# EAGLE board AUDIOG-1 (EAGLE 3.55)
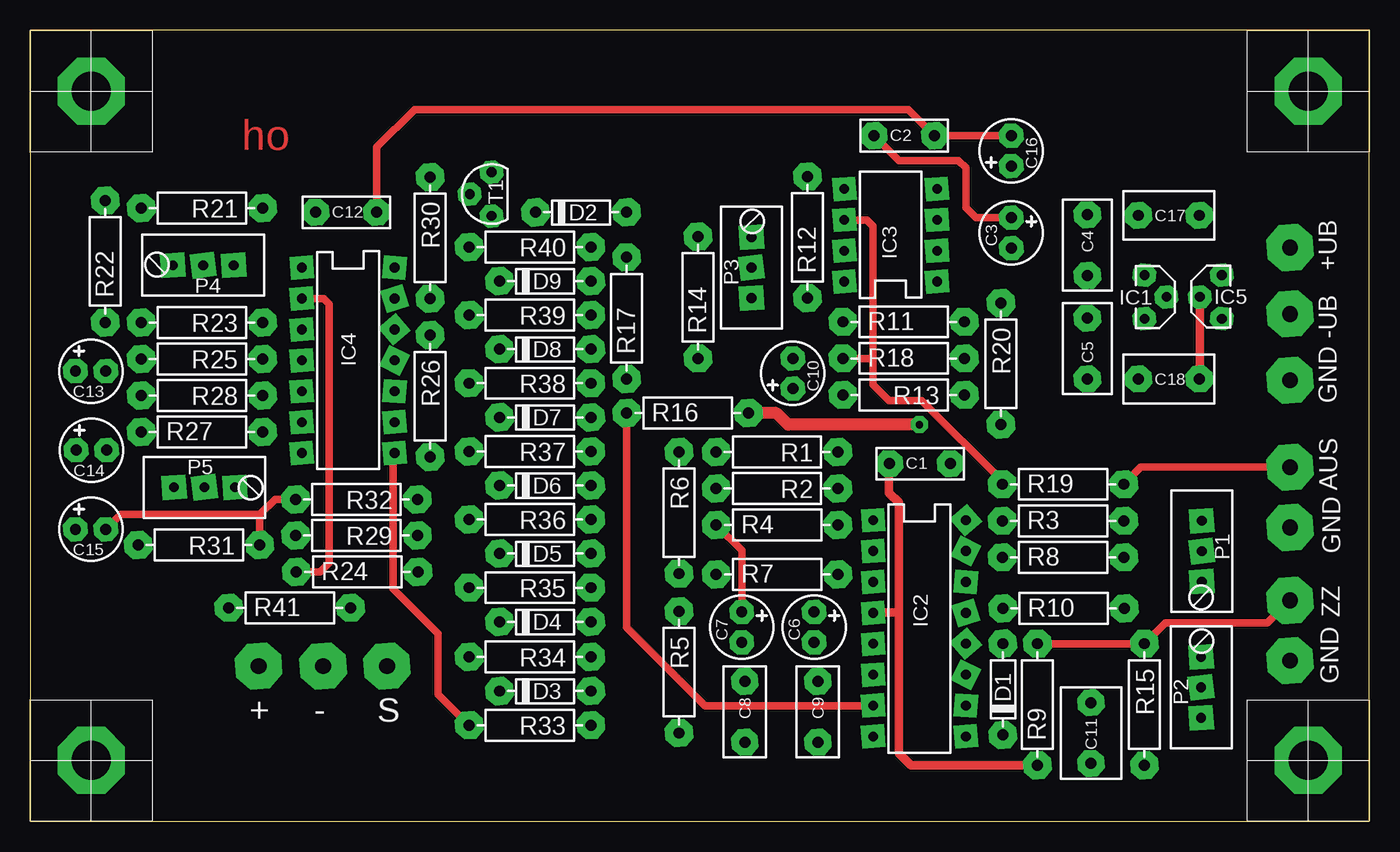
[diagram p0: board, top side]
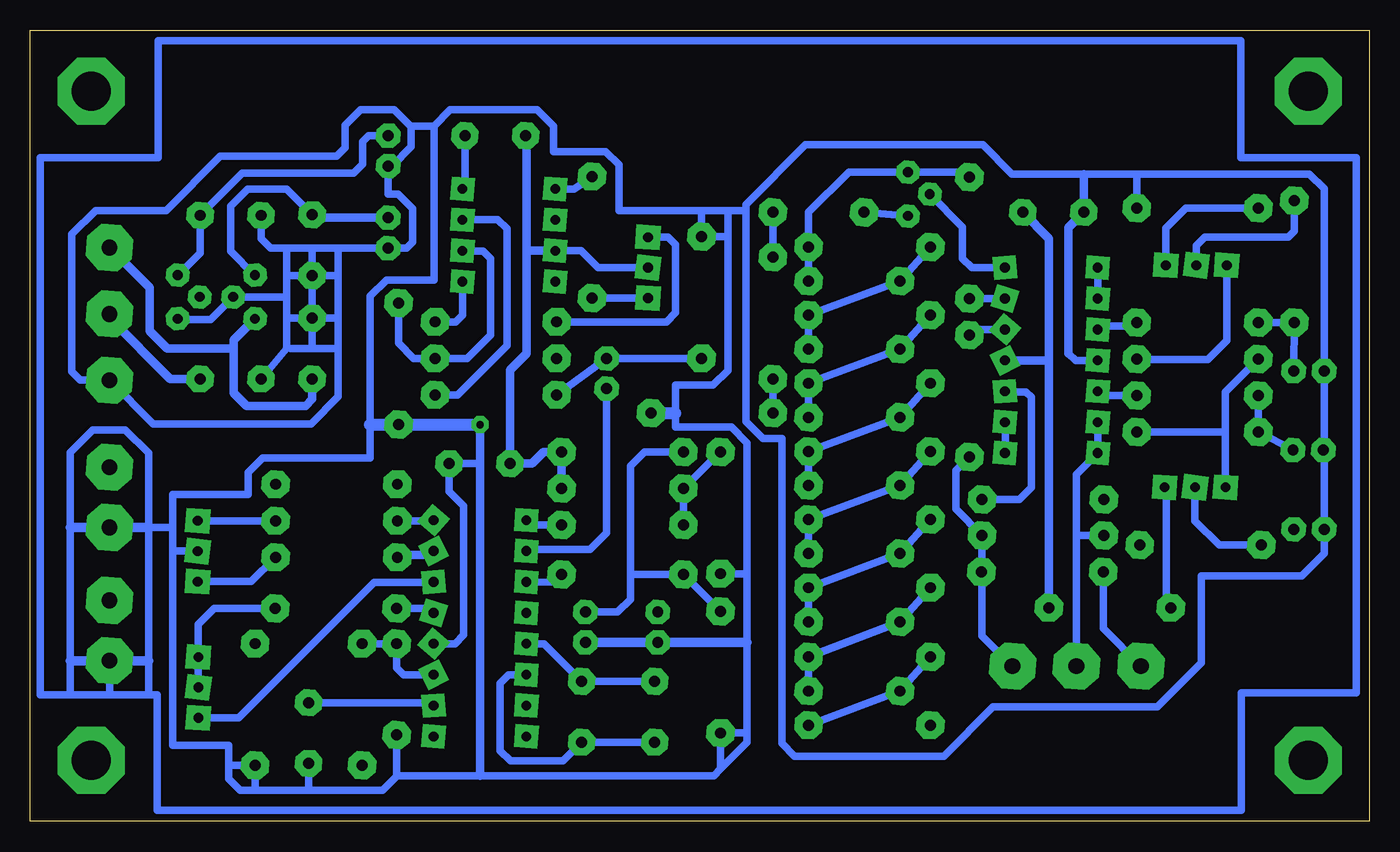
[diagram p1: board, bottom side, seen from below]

Size 110 x 65 mm. Coordinates in mm from the lower left corner, seen from the top.
Outline: 110,0 110,65 0,65 0,0 110,0
Copper layers used: Top, Bottom

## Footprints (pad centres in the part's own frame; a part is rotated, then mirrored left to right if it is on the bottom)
AD-3,8 = drill 1.3 pad 3.8 octagon:  0,0
5-2,8 = drill 0.9 pad 2.2 octagon:  0,0;  5,0
5-R2,5 = drill 0.9 pad 2 octagon:  0,0;  0,2.5
-4,0 = drill 0.9 pad 2.2 octagon:  0,0;  5,0
5-3,5 = drill 0.9 pad 2.2 octagon:  0,0;  5,0
5-5,0 = drill 0.9 pad 2.2 octagon:  0,0;  5,0
7,5 = drill 0.9 pad 2.3 octagon:  0,0;  7.5,0
L00 = drill 0.8 pad 1.9 octagon:  -1.8,1.8;  0,3.6;  0,0
L16 = drill 0.8 pad 1.9 square:  0,0;  2.54,0;  5.08,0;  7.62,0;  10.16,0;  12.7,0;  15.24,0;  17.78,0;  17.78,7.62;  15.24,7.62;  12.7,7.62;  10.16,7.62;  7.62,7.62;  5.08,7.62;  2.54,7.62;  0,7.62
L08 = drill 0.8 pad 1.9 square:  0,0;  2.54,0;  5.08,0;  7.62,0;  7.62,7.62;  5.08,7.62;  2.54,7.62;  0,7.62
L14 = drill 0.8 pad 1.9 square:  0,0;  2.54,0;  5.08,0;  7.62,0;  10.16,0;  12.7,0;  15.24,0;  15.24,7.62;  12.7,7.62;  10.16,7.62;  7.62,7.62;  5.08,7.62;  2.54,7.62;  0,7.62
IMM-S1 = drill 0.8 pad 2 square:  0,0;  2.5,0;  -2.5,0
10 = drill 0.9 pad 2.3 octagon:  0,0;  10,0
-TO92 = drill 0.8 pad 1.9 octagon:  1.8,1.8;  3.6,0;  0,0

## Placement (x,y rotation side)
+  +  [AD-3,8]  18.75,12.75 0 top
+UB  +UB  [AD-3,8]  103.5,47.15 0 top
-  -  [AD-3,8]  24.05,12.75 0 top
-UB  -UB  [AD-3,8]  103.5,41.7 0 top
AUS  Aus  [AD-3,8]  103.5,29.1 0 top
BEF1  [F10]  5,60 0 top
BEF2  [F10]  105,60 0 top
BEF3  [F10]  5,5 0 top
BEF4  [F10]  105,5 0 top
C1  100n  [5-2,8]  70.6,29.4 0 top
C2  100n  [5-2,8]  69.3,56.35 0 top
C3  47u  [5-R2,5]  80.6,47.1 0 top
C4  220n  [-4,0]  86.85,49.85 270 top
C5  330n  [-4,0]  86.85,36.35 90 top
C6  10u  [5-R2,5]  64.4,14.7 0 top
C7  10u  [5-R2,5]  58.45,14.7 0 top
C8  Abgl  [5-3,5]  58.7,11.5 270 top
C9  47n5  [5-3,5]  64.7,11.5 270 top
C10  22u  [5-R2,5]  62.65,38.05 180 top
C11  1u  [5-5,0]  87.15,9.75 270 top
C12  100n  [5-2,8]  23.45,50.05 0 top
C13  22u  [5-R2,5]  6.2,37 90 top
C14  22u  [5-R2,5]  6.25,30.5 90 top
C15  22u  [5-R2,5]  6.2,24 90 top
C16  47u  [5-R2,5]  80.6,56.35 180 top
C17  220n  [-4,0]  91.05,49.8 0 top
C18  330n  [-4,0]  91.05,36.35 0 top
D1  1N4148  [7,5]  79.9,7.1 90 top
D2  1N4148  [7,5]  41.5,50.05 0 top
D3  1N4148  [7,5]  38.55,10.7 0 top
D4  1N4148  [7,5]  38.55,16.4 0 top
D5  1N4148  [7,5]  38.55,22 0 top
D6  1N4148  [7,5]  38.55,27.6 0 top
D7  1N4148  [7,5]  38.55,33.2 0 top
D8  1N4148  [7,5]  38.55,38.8 0 top
D9  1N4148  [7,5]  38.55,44.4 0 top
GND  GND  [AD-3,8]  103.5,36.25 0 top
GND1  [AD-3,8]  103.5,13.2 0 top
GND2  GND  [AD-3,8]  103.5,24.15 0 top
IC1  78L15  [L00]  91.55,44.9 180 top
IC2  XR2206  [L16]  69.25,24.75 270 top
IC3  TL071  [L08]  74.5,44.35 90 top
IC4  TL074  [L14]  22.3,45.5 270 top
IC5  79L15  [L00]  97.9,41.3 0 top
P1  20k  [IMM-S1]  96.25,22.2 270 top
P2  500  [IMM-S1]  96.2,11 90 top
P3  10k  [IMM-S1]  59.25,45.5 90 top
P4  500  [IMM-S1]  14.2,45.7 180 top
P5  200  [IMM-S1]  14.3,27.45 0 top
R1  47k  [10]  66.35,30.35 180 top
R2  82k  [10]  66.35,27.35 180 top
R3  10k  [10]  79.85,24.7 0 top
R4  33k  [10]  56.35,24.35 0 top
R5  47k  [10]  53.3,17.25 270 top
R6  33k  [10]  53.3,30.35 270 top
R7  33k  [10]  56.35,20.3 0 top
R8  10k  [10]  79.85,21.7 0 top
R9  4k7  [10]  82.75,4.6 90 top
R10  120  [10]  79.9,17.5 0 top
R11  4.7k  [10]  66.75,41.05 0 top
R12  4.7k  [10]  63.85,43 90 top
R13  100  [10]  76.75,35.05 180 top
R14  33k  [10]  54.85,38.05 90 top
R15  300  [10]  91.55,14.6 270 top
R16  4M7  [10]  49,33.55 0 top
R17  2k4  [10]  49,36.35 90 top
R18  680  [10]  66.75,38.05 0 top
R19  47  [10]  79.85,27.7 0 top
R20  [10]  79.75,42.6 270 top
R21  3k3  [10]  19.1,50.4 180 top
R22  10k  [10]  6.15,41 90 top
R23  100  [10]  19.1,41 180 top
R24  1M  [10]  21.85,20.5 0 top
R25  2k2  [10]  19.1,38 180 top
R26  100  [10]  32.85,39.95 270 top
R27  10k  [10]  9.1,32 0 top
R28  100  [10]  19.1,35 180 top
R29  1M  [10]  31.8,23.5 180 top
R30  680  [10]  32.85,52.95 270 top
R31  10k  [10]  18.85,22.7 180 top
R32  100  [10]  31.8,26.45 180 top
R33  270  [10]  46.05,7.9 180 top
R34  1k  [10]  46.05,13.5 180 top
R35  2k  [10]  46.05,19.2 180 top
R36  3k9  [10]  46.05,24.8 180 top
R37  8k2  [10]  46.05,30.4 180 top
R38  16k  [10]  46.05,36 180 top
R39  33k  [10]  46.05,41.6 180 top
R40  68k  [10]  46.05,47.2 180 top
R41  1k3  [10]  16.3,17.55 0 top
SCHL  S  [AD-3,8]  29.3,12.75 0 top
T1  BC550C  [-TO92]  37.9,49.75 90 top
Z-OUT  Zum Zhler  [AD-3,8]  103.5,18.15 90 top

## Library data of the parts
+ +UB - -UB AUS GND GND1 GND2 SCHL Z-OUT = PADS
BEF1-BEF4 = MECHANIK
C1-C18 D1-D9 IC2-IC4 R1-R41 T1 = EAGLE
IC1 IC5 = U-STABI
P1-P5 = POTIS

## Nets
+15V: C1. C2. C3. C4. IC1. IC2. IC3. P3. R1. R2. R9.
+UB: +UB. C5. IC1.
-15V: C2. C12. C16. C17. IC3. IC4. IC5. R41.
-UB: -UB. C18. IC5.
AUS: AUS. R19.
GND: C1. C3. C4. C5. C6. C7. C11. C12. C13. C14. C15. C16. C17. C18. D1. GND1. GND2. GND. IC1. IC2. IC4. IC5. P1. R5. R6. R14. R15. R16. R20. R21.
N$1: IC2. R3.
N$2: IC2. R8.
N$3: P1. R3.
N$4: P1. R8.
N$5: IC2. P2.
N$6: IC2. R10.
N$7: P2. R10.
N$8: C6. R1. R5. R7.
N$10: C8. C9. IC2.
N$11: C11. IC2.
N$12: IC2. R4.
N$13: IC2. R7.
N$14: P5. R41.
N$15: C7. R2. R4. R6.
N$16: C10. IC2.
N$17: C10. R13. R14.
N$18: C8. C9. IC2.
N$20: -. IC4. R29.
N$22: IC2. R16. R17.
N$23: +. IC4. R24.
N$24: R24. R26. R29. SCHL.
N$25: P4. R22.
N$26: P5. R31.
N$27: C13. R22. R23.
N$28: IC4. R23.
N$29: P3. R11.
N$30: C15. R31. R32.
N$31: IC4. R32.
N$32: IC4. R26.
N$33: IC4. R33.
N$34: IC4. R28.
N$35: IC3. R13.
N$36: IC3. R18. R20.
N$37: P4. R21.
N$38: P5. R25. R27.
N$39: D9. R30. R40. T1.
N$40: IC4. R30.
N$41: P4. R25.
N$42: P3. R12.
N$43: IC4. T1.
N$44: D3. R33. R34.
N$45: D3. D4. R34. R35.
N$46: D4. D5. R35. R36.
N$47: D5. D6. R36. R37.
N$48: D6. D7. R37. R38.
N$49: D7. D8. R38. R39.
N$50: D8. D9. R39. R40.
N$51: IC3. R18. R19.
N$52: D2. T1.
N$53: D2. R17.
N$56: C14. R27. R28.
N$57: IC3. R12.
N$86: IC3. R11.
TTL-OUT: D1. IC2. R9. R15. Z-OUT.

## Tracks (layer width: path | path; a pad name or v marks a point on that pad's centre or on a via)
+15V
  Top 0.6: C3. 77.7,49.6 76.85,50.45 76.85,53.7 76.25,54.3 71.35,54.3 69.3,56.35
  Top 0.7: 70.6,29.4 70.55,29.4 70.55,27 71.35,26.2 71.35,17.15 | 71.35,17.15 71.35,5.6 72.35,4.6 82.75,4.6 | 69.25,17.13 69.25,17.15 71.35,17.15
  Bottom 0.6: 69.25,56.35 69.3,56.35 | IC1. 91.6,44.9 93.55,46.85 93.55,50.55 92.15,51.95 88.95,51.95 86.85,49.85 | 66.88,46.89 66.85,46.9 64.75,46.9 63.35,45.5 59.25,45.5
  Bottom 0.7: 69.25,46.9 69.25,56.35 | 69.25,46.9 69.25,38.45 70.6,37.1 70.6,29.4 68.8,29.4 67.85,30.35 66.35,30.35 66.35,27.35 | C3. 86.6,49.6 86.85,49.85 | 66.88,46.89 66.9,46.9 69.25,46.9
+UB
  Bottom 0.7: 91.55,41.3 93.3,39.55 93.3,38.85 | 86.85,36.35 86.85,34.7 87.4,34.15 92.25,34.15 93.3,35.2 93.3,38.85 | 93.3,38.85 98.75,38.85 100.2,40.3 100.2,43.85 +UB.
-15V
  Top 0.6: C12. 28.45,55.4 31.55,58.5 72.15,58.5 C2. 80.6,56.35
  Bottom 0.6: 97.9,44.9 97.85,44.9 96.05,46.7 C17. 92.6,53.25 83.45,53.25 82.7,54 82.7,55.85 82.2,56.35 80.6,56.35 | 74.5,51.97 74.3,52.15 C2.
  Bottom 0.7: 29.92,37.88 29.9,37.85 26.3,37.85 | 26.3,37.85 26.3,47.9 C12. | R41. 26.3,37.85
-UB
  Top 0.7: 96.1,43.1 96.1,36.35 C18.
  Bottom 0.7: C18. 98.5,36.35 103.5,41.35 -UB.
AUS
  Top 0.6: R19. 91.25,29.1 AUS.
GND  (via drill 0.6 pad 1.4)
  Top 1: v73.05,32.6 62.25,32.6 61.3,33.55 R16.
  Bottom 0.3: 88.95,41.35 88.95,41.3
  Bottom 0.6: 3.7,30.5 C14. | 3.7,30.5 C13. 3.7,52 4.9,53.2 19.1,53.2 | 3.7,30.5 C15. 3.7,22 5.55,20.15 13.8,20.15 13.8,13 17.4,9.4 30.9,9.4 34.95,5.35 47.2,5.35 48.25,6.4 48.25,31.45 49.8,31.45 51.2,32.85 51.2,50.2 | C1. 75.6,29.35 | C1. 75.6,27.1 74.4,25.9 74.4,15.3 75.1,14.6 76.85,14.6 76.87,14.59 | 73.05,29.4 C1. | C16. 80.6,53.3 | 84.7,47.1 86.85,47.1 | 84.7,47.1 80.6,47.1 79.1,47.1 78.6,47.6 78.6,50.35 79.8,51.55 80.6,51.55 C16. | 84.7,47.1 84.7,44.85 | 84.7,44.85 84.7,41.35 | 86.85,47.1 C4. | C5. 86.85,44.8 | 84.7,44.85 C4. | 88.95,43.1 93.35,43.1 95.2,41.25 97.9,41.25 IC5. | 88.95,44.8 88.95,44.85 C4. | 88.95,44.8 88.95,43.1 | 88.95,43.1 88.95,41.35 C5. | 84.7,41.35 C5. | 84.7,38.85 86.85,38.85 | 86.85,38.85 88.6,38.85 | 84.7,41.35 84.7,38.85 | 84.7,38.85 84.7,34.9 86.95,32.65 99.9,32.65 GND. 105.9,36.25 106.6,36.95 106.6,48.25 104.65,50.2 98.85,50.2 94.4,54.65 84.85,54.65 84.15,55.35 84.15,57.2 82.85,58.5 80.1,58.5 78.75,57.15 | C5. 86.85,38.85 | 88.95,41.3 88.95,38.85 91.05,36.35 | 88.95,47.1 88.95,44.8 | 86.85,47.1 88.95,47.1 | 88.95,47.1 90.25,47.1 91.05,47.9 91.05,49.8 | 22.3,37.88 22.25,37.85 24.1,37.85 24.7,38.45 | 19.1,53.2 19.1,50.4 | 52.7,48.05 52.7,37.05 53.9,35.85 57,35.85 57,33.55 57,32.4 52.4,32.4 51.1,31.1 51.1,20.35 | 52.7,48.05 52.7,50.2 | 52.7,50.2 54.85,50.2 | 54.85,50.2 61.65,50.2 61.65,53.95 62.75,55.05 67,55.05 67,57.15 68.35,58.5 75.5,58.5 76.85,57.15 | 98.3,22.15 98.3,6.25 93.7,6.25 93.7,4.6 | 96.25,22.2 98.3,22.2 98.3,22.15 | 76.85,57.15 76.85,44.5 80.75,44.5 82.1,43.15 82.1,32.6 82.1,29.85 90.9,29.85 92.1,28.65 92.1,26.85 98.3,26.85 98.3,24.15 | C16. 80.3,53.85 78.7,55.45 78.7,57.1 78.75,57.15
  Bottom 0.6: 19.1,53.2 23.45,53.2 29.35,53.2 31.75,55.6 46.3,55.6 51.2,50.7 51.2,50.2 | 51.1,20.35 R6. | 52.7,48.05 R14. 54.85,50.2 | 51.1,7.25 51.1,6.5 53.3,4.3 | 51.1,7.25 51.1,14.7 51.1,20.35 | 53.3,4.3 53.85,3.75 73.05,3.75 79.85,3.75 | 51.1,7.25 R5. 53.3,4.3 | 79.9,7.1 79.9,3.75 79.85,3.75 | 79.85,3.75 81.05,2.55 87.15,2.55 | 91.55,2.55 87.15,2.55 | 91.55,2.55 92.75,2.55 93.7,3.5 93.7,4.6 | 87.15,2.55 C11. | 91.55,2.55 R15. 93.7,4.6 | 98.3,24.15 98.3,22.15 | 106.75,10.4 109.2,10.4 109.2,54.55 99.5,54.55 99.5,64.15 10.55,64.15 10.55,54.55 1.05,54.55 1.05,10.55 10.5,10.55 10.5,0.9 99.6,0.9 99.6,1.7 | 106.75,10.4 103.5,10.4 | 103.5,10.4 100.3,10.4 | 100.3,10.4 99.6,10.4 99.6,1.75 | 100.3,10.4 100.3,13.2 100.3,24.15 | 100.3,24.15 100.3,30.25 102.2,32.15 104.9,32.15 106.75,30.3 106.75,24.15 106.75,13.2 106.75,10.4 | 103.5,10.4 GND1. | 103.45,24.15 GND2. | 100.3,24.15 98.3,24.15 | 52.7,50.2 51.2,50.2 | 76.85,57.15 78.75,57.15
  Bottom 0.7: v73.05,32.6 73.05,29.4 73.05,3.75 | 24.7,38.45 24.7,48.8 23.45,50.05 23.45,53.2
  Bottom 0.8: 64.4,14.7 58.45,14.7 51.1,14.7 | 100.3,13.2 GND1. 106.75,13.2 | 100.3,24.15 103.45,24.15 106.75,24.15
  Bottom 1: 82.1,32.6 R20. v73.05,32.6 | R16. 57,33.55
N$1
  Bottom 0.6: 76.85,24.75 IC2. 77.05,24.7 79.85,24.7
N$2
  Bottom 0.7: 76.87,22.21 77.3,21.9 79.6,21.9 79.85,21.7
N$3
  Bottom 0.6: R3. P1.
N$4
  Bottom 0.6: R8. 91.85,19.7 96.25,19.7
N$5
  Bottom 0.6: 76.87,19.67 76.9,19.65 81.75,19.65 92.9,8.5 P2.
N$6
  Bottom 0.6: 76.87,17.13 77.2,17.5 79.9,17.5
N$7
  Bottom 0.6: 96.2,11 96.2,13.5 96.2,16.2 94.9,17.5 R10.
N$8
  Bottom 0.6: R1. 59.55,30.35 60.7,29.2 60.7,20.3 | 60.7,20.3 60.7,18.25 61.75,17.2 C6. | 60.7,20.3 56.35,20.3 53.3,17.25
N$9  (via drill 3.2 pad 5.5)
  other vias: 5,5
N$10
  Bottom 0.6: 69.25,12.05 70.7,12.05 71.4,11.35 71.4,5.8 70.55,4.95 66.25,4.95 C9. C8.
N$11
  Bottom 0.6: 76.87,9.51 76.9,9.5 77.25,9.75 87.15,9.75
N$12
  Bottom 0.6: 69.25,24.75 69.2,24.75 69.2,24.35 R4.
N$13
  Bottom 0.6: R7. 66.3,20.3 66.95,19.65 69.25,19.67
N$14
  Bottom 0.6: 16.8,27.45 16.65,27.3 16.65,17.9 16.3,17.55
N$15
  Top 0.6: C7. 58.45,22.25 56.35,24.35
  Bottom 0.6: 56.35,24.35 R2. 53.35,30.35 53.3,30.35
N$16
  Bottom 0.6: 69.25,22.2 69.25,22.21 69.25,22.35 64,22.35 62.65,23.7 C10.
N$17
  Bottom 0.6: R13. 62.65,38.05 54.85,38.05
N$18
  Bottom 0.6: 58.7,11.5 64.7,11.5 67.8,14.59 69.25,14.59
N$19  (via drill 3.2 pad 5.5)
  other vias: 5,60
N$20
  Bottom 0.6: 24.05,23.5 24.05,28.5 22.3,30.25 22.3,30.26 22.25,30.25 22.3,30.3 22.3,32.8 | 24.05,23.5 R29. | -. 24.05,23.5
N$21  (via drill 3.2 pad 5.5)
  other vias: 105,60
N$22
  Top 0.6: 49,33.55 49,15.95 55.45,9.5 67.35,9.5 | 67.35,9.5 67.4,9.5 | 69.25,9.51 69.25,9.5 67.35,9.5
  Bottom 0.6: 49,33.55 49,36.35
N$23
  Top 0.6: 22.3,42.96 24.1,42.95 24.55,42.5 24.55,21.25 23.8,20.5 21.85,20.5 21.8,20.5
  Bottom 0.6: 22.3,45.5 22.3,42.96 22.3,42.95 | 21.85,20.5 21.85,15.85 +.
N$24
  Bottom 0.6: 31.8,20.55 R24. | 31.8,20.55 31.8,23.5 33.95,25.65 33.95,28.85 R26. | 31.8,20.55 31.8,15.25 SCHL.
N$25
  Bottom 0.6: 14.2,45.7 14.2,47.3 13.5,48 6.65,48 6.15,48.5 R22.
N$26
  Bottom 0.6: 14.3,27.45 14.3,24.7 12.3,22.7 R31.
N$27
  Bottom 0.6: R23. 6.15,41 6.2,37.2 6.2,37
N$28
  Bottom 0.6: 22.3,40.42 22,40.7 19.4,40.7 19.1,41
N$29
  Bottom 0.6: 66.75,41.05 57.75,41.05 57,41.8 57,47.4 57.6,48 59.25,48
N$30
  Top 0.6: 6.2,24 7.4,25.2 18.85,25.2 | 18.85,25.2 20.1,26.45 R32. | 18.85,25.2 18.85,22.7
N$31
  Bottom 0.6: 31.8,26.45 28.75,26.45 27.75,27.45 27.75,34.85 28.2,35.3 29.9,35.3 29.92,35.34
N$32
  Bottom 0.6: 32.85,39.95 32.85,39.9 32.35,40.42 29.92,40.42
N$33
  Top 0.6: 29.92,30.26 29.8,30.15 29.8,19.1 33.5,15.4 33.5,10.45 R33.
  Bottom 0.6: 29.9,32.8 29.85,32.8 | 29.9,32.8 29.92,32.8 | 29.92,30.26 29.9,30.3 29.9,32.8
N$34
  Bottom 0.6: 19.05,35 19.1,35 22.3,35 22.3,35.34
N$35
  Bottom 0.6: 74.45,49.4 74.5,49.43 | 74.4,49.45 71.6,49.45 70.85,48.7 70.85,39.1 74.9,35.05 76.75,35.05
  Bottom 0.7: 74.4,49.45 74.45,49.4
N$36
  Bottom 0.3: 74.5,46.85 74.5,46.89
  Bottom 0.6: 74.5,46.85 72.8,46.85 72.2,46.25 72.2,39.95 74.1,38.05 R18. 78.5,38.05 79.75,39.3 79.75,42.6
N$37
  Bottom 0.6: P4. 16.7,48.75 15.05,50.4 R21. 9,50.4
N$38
  Bottom 0.6: 11.8,27.4 P5. 11.8,32 | R25. 11.8,35.3 11.8,32 | 11.8,32 R27.
N$39
  Bottom 0.6: 46.05,44.35 D9. 46.05,47.2 46.05,50.05 42.75,53.35 37.9,53.35 33.25,53.35 32.85,52.95
N$40
  Bottom 0.6: 29.92,42.96 30.05,42.95 R30.
N$41
  Bottom 0.6: 11.7,45.7 11.7,39.5 13.25,37.95 19.05,37.95 19.1,38
N$42
  Bottom 0.6: P3. 63.85,43
N$43
  Bottom 0.6: IC4. 32.65,45.5 33.4,46.25 33.4,48.85 36.1,51.55
N$44
  Bottom 0.6: R34. 38.55,10.7 46.05,7.9
N$45
  Bottom 0.6: R35. 38.55,16.4 46.05,13.5 D3.
N$46
  Bottom 0.6: R36. 38.55,22 46.05,19.2 D4.
N$47
  Bottom 0.6: R37. 38.55,27.6 46.05,24.8 D5. 46.05,21.95
N$48
  Bottom 0.6: R38. 38.55,33.2 46.05,30.4 D6.
N$49
  Bottom 0.6: R39. 38.55,38.8 46.05,36 D7.
N$50
  Bottom 0.6: R40. 38.55,44.4 46.05,41.6 D8. 46.05,38.75
N$51
  Top 0.6: 66.88,49.43 66.9,49.4 68.75,49.4 69.25,48.9 69.25,38.05 | 66.75,38.05 69.25,38.05 | 69.25,38.05 69.25,35.9 70.55,34.6 73.2,34.6 79.85,27.95 79.85,27.7
N$52
  Bottom 0.6: T1. 41.5,50.05
N$53
  Bottom 0.6: R17. D2.
N$54  (via drill 3.2 pad 5.5)
  other vias: 105,5
N$56
  Bottom 0.6: 6.25,30.5 6.2,30.5 9.1,32 R28.
N$57
  Bottom 0.6: 66.88,51.97 65.35,51.97 R12.
N$86
  Bottom 0.6: 74.5,44.35 74.5,41.6 75.05,41.05 R11.
TTL-OUT
  Top 0.6: R9. 91.55,14.6 93.25,16.3 101.65,16.3 Z-OUT.
  Bottom 0.6: 76.87,12.05 79.35,12.05 79.9,12.6 D1. R9.

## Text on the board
Top: ho
tPlace: +UB | -UB | GND | AUS | GND | ZZ | GND | + | - | S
